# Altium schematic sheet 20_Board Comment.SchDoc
size 337 x 236 mm
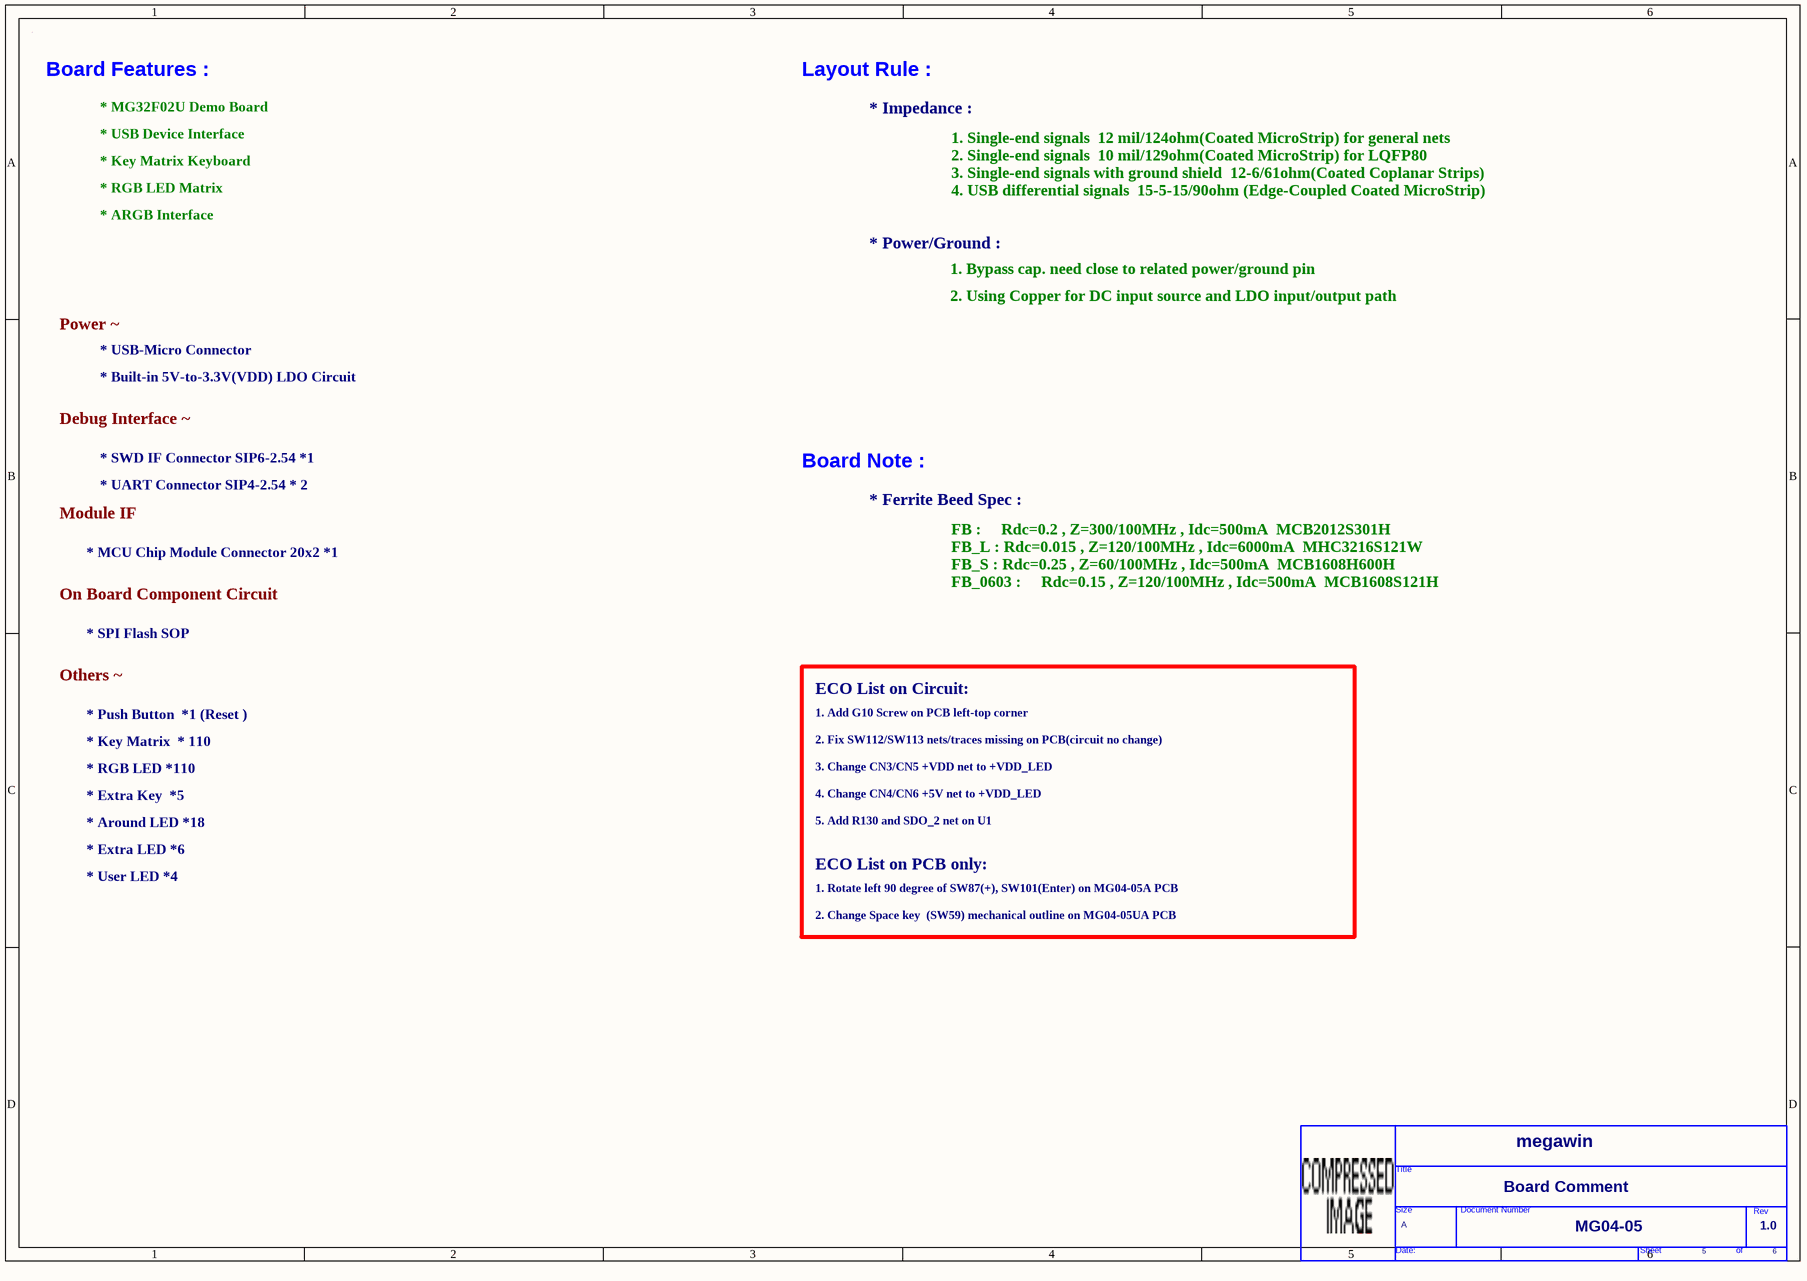
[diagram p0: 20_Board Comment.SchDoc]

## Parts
*  OrgName: megawin  Doc: MG04-05  RevCode: 1.0  Title: Board Comment  Page Size: A  Page Number: 5  Page Count: 6  (hidden comment: TitleBlock_MegaWin)  (graphical)

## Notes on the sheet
- Board Features :
- * MG32F02U Demo Board
- * USB Device Interface
- Layout Rule :
- * Impedance :
- * RGB LED Matrix
- * Key Matrix Keyboard
- * ARGB Interface
- * Power/Ground :
- 1. Bypass cap. need close to related power/ground pin
- 1. Single-end signals  12 mil/124ohm(Coated MicroStrip) for general nets
  2. Single-end signals  10 mil/129ohm(Coated MicroStrip) for LQFP80
  3. Single-end signals with ground shield  12-6/61ohm(Coated Coplanar Strips)
  4. USB differential signals  15-5-15/90ohm (Edge-Coupled Coated MicroStrip)
- Power ~
- 2. Using Copper for DC input source and LDO input/output path
- * Built-in 5V-to-3.3V(VDD) LDO Circuit
- * USB-Micro Connector
- Debug Interface ~
- * SWD IF Connector SIP6-2.54 *1
- Board Note :
- Module IF
- * UART Connector SIP4-2.54 * 2
- * Ferrite Beed Spec :
- On Board Component Circuit
- * MCU Chip Module Connector 20x2 *1
- Others ~
- * SPI Flash SOP
- FB :     Rdc=0.2 , Z=300/100MHz , Idc=500mA  MCB2012S301H
  FB_L : Rdc=0.015 , Z=120/100MHz , Idc=6000mA  MHC3216S121W
  FB_S : Rdc=0.25 , Z=60/100MHz , Idc=500mA  MCB1608H600H
  FB_0603 :     Rdc=0.15 , Z=120/100MHz , Idc=500mA  MCB1608S121H
- * Push Button  *1 (Reset )
- * Key Matrix  * 110
- 2. Fix SW112/SW113 nets/traces missing on PCB(circuit no change)
- 1. Add G10 Screw on PCB left-top corner
- ECO List on Circuit:
- * RGB LED *110
- * Extra Key  *5
- 3. Change CN3/CN5 +VDD net to +VDD_LED
- 4. Change CN4/CN6 +5V net to +VDD_LED
- * Around LED *18
- * User LED *4
- * Extra LED *6
- 5. Add R130 and SDO_2 net on U1
- ECO List on PCB only:
- 2. Change Space key  (SW59) mechanical outline on MG04-05UA PCB
- 1. Rotate left 90 degree of SW87(+), SW101(Enter) on MG04-05A PCB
